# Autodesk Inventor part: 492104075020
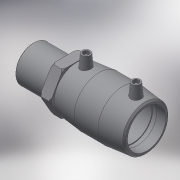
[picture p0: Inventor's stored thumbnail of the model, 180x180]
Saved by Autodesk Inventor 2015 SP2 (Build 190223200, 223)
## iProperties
Created: 2017-06
Part Number: 492104075020
Material: Generic
Description: PLASSON Male Transition Coupler 75 x 2"
Document SubType Name: Modeling
Designer: KIM
Mass: 513.691 g
Surface Area: 979.298 cm^2
Volume: 513.691 cm^3
Density: 1 g/cm^3
Appearance: Default
Author: KIM
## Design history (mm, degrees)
derived "492104.ipt"
feature "Solid1::492104.ipt"
tag "TaggingFeature1"
body "Solid1"
other parameters: "d0" = 126, "d1" = 75, "d2" = 98, "d3" = 61, "d4" = 42, "d5" = 88.2, "d6" = 71.25, "d7" = 75, "d8" = 168 deg, "d10" = 24.4, "d11" = 8.13333, "d29" = 64, "d30" = 14, "d31" = 44.1, "d34" = 5 deg, "d41" = 4, "d42" = 14, "d43" = 0, "d48" = 3, "d49" = 0, "d57" = 59, "d58" = 59.614, "d59" = 47.6912, "d60" = 36.9, "d61" = 98, "d62" = 1.19228, "d65" = 2.94, "d70" = 0.1, "d71" = 41, "d72" = 10.25, "d73" = 24.4, "d75" = 0, "d_" = 75, "L_" = 167, "L_1" = 61, "D_1" = 98, "A_" = 64, "d_2" = 12, "L_2" = 41, "D_" = 59, "R_" = 59.614
